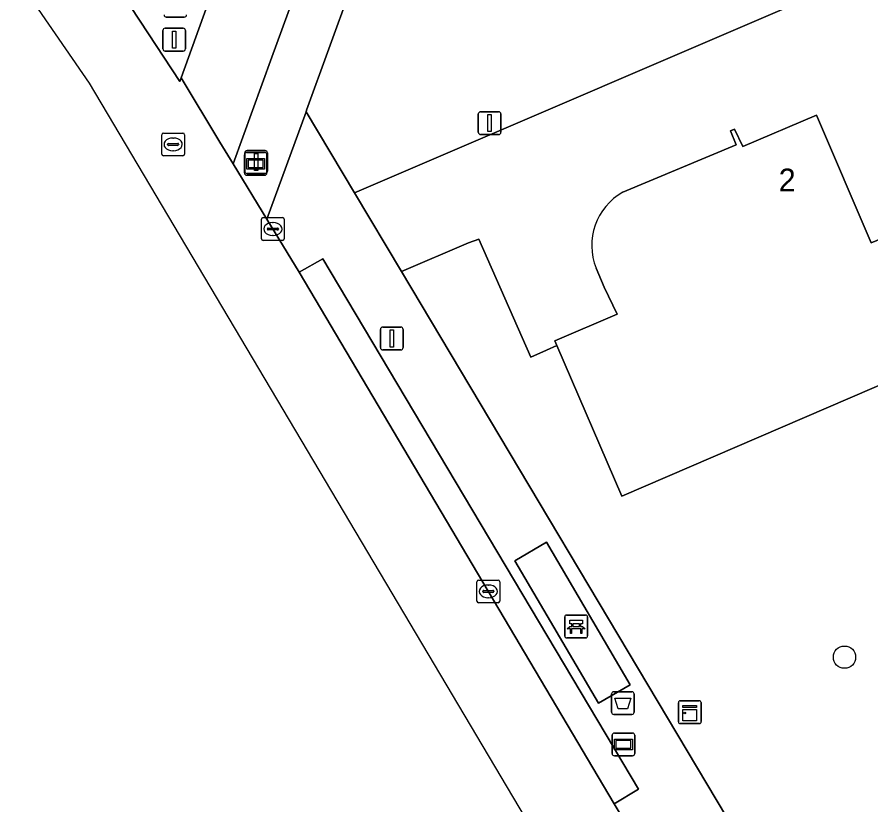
# Model space of a CAD drawing. Extents: x 156661 to 157576, y 383570 to 384425.
# Drawn here: x 156665.87 to 156703.3, y 383837.35 to 383871.9 of the extents above; entities that cross this region are included whole.
import ezdxf

# ---------------------------------------------------------------- set-up
doc = ezdxf.new("R2010")
doc.units = 0
for name, color, linetype in [('IMGEO_Afvalbak', 7, 'Continuous'), ('IMGEO_Bank', 7, 'Continuous'), ('IMGEO_Boom', 7, 'Continuous'), ('IMGEO_Fietspad_open', 7, 'Continuous'), ('IMGEO_Groenvoorziening', 7, 'Continuous'), ('IMGEO_Informatiebord', 7, 'Continuous'), ('IMGEO_Kast', 7, 'Continuous'), ('IMGEO_Kolk', 7, 'Continuous'), ('IMGEO_Lichtmast', 7, 'Continuous'), ('IMGEO_OVBaan_gesloten', 7, 'Continuous'), ('IMGEO_Pand', 7, 'Continuous'), ('IMGEO_Pand_nummerreeks', 7, 'Continuous'), ('IMGEO_Rioolput', 7, 'Continuous'), ('IMGEO_Verkeersbordpaal', 7, 'Continuous'), ('IMGEO_Verkeerseiland_groen', 7, 'Continuous'), ('IMGEO_Verkeersregelinstallatiepaal', 7, 'Continuous'), ('IMGEO_Voetpad_open', 7, 'Continuous'), ('IMGEO_Wegwijzer', 7, 'Continuous')]:
    doc.layers.add(name, color=color, linetype=linetype)

msp = doc.modelspace()

# ---------------------------------------------------------------- linework, layer by layer
at = {"layer": 'IMGEO_Afvalbak'}
for p, q in [((156692.03, 383842.313), (156692.82, 383842.313)), ((156692.82, 383842.313), (156692.03, 383842.313)), ((156691.93, 383841.413), (156691.93, 383842.213)), ((156691.93, 383842.213), (156691.93, 383841.413)), ((156692.92, 383842.213), (156692.92, 383841.413)), ((156692.92, 383841.413), (156692.92, 383842.213)), ((156692.82, 383841.313), (156692.03, 383841.313)), ((156692.03, 383841.313), (156692.82, 383841.313))]:
    msp.add_line(p, q, dxfattribs=at)
msp.add_lwpolyline([(156692.073, 383842.027), (156692.777, 383842.027), (156692.628, 383841.557), (156692.222, 383841.557), (156692.073, 383842.027)], dxfattribs=at)
for centre, start, end in [((156692.03, 383842.213), 90, 180), ((156692.03, 383842.213), 90, 180), ((156692.82, 383842.213), 0, 90), ((156692.82, 383842.213), 360, 90), ((156692.03, 383841.413), 180, 270), ((156692.03, 383841.413), 180, 270), ((156692.82, 383841.413), 270, 0), ((156692.82, 383841.413), 270, 0)]:
    msp.add_arc(centre, 0.1, start, end, dxfattribs=at)
at = {"layer": 'IMGEO_Bank'}
for p, q in [((156689.956, 383845.674), (156690.797, 383845.674)), ((156690.797, 383845.674), (156689.956, 383845.674)), ((156689.881, 383844.749), (156689.881, 383845.59)), ((156689.881, 383845.59), (156689.881, 383844.749)), ((156690.19, 383845.18), (156690.19, 383845.286)), ((156690.234, 383845.286), (156690.234, 383845.18)), ((156690.522, 383845.292), (156690.24, 383845.292)), ((156690.528, 383845.18), (156690.528, 383845.286)), ((156690.572, 383845.286), (156690.572, 383845.18)), ((156690.881, 383845.599), (156690.881, 383844.758)), ((156690.881, 383844.758), (156690.881, 383845.599)), ((156690.578, 383845.072), (156690.185, 383845.072)), ((156690.24, 383845.174), (156690.522, 383845.174)), ((156690.806, 383844.674), (156689.965, 383844.674)), ((156689.965, 383844.674), (156690.806, 383844.674))]:
    msp.add_line(p, q, dxfattribs=at)
for points in [[(156690.184, 383845.292), (156690.098, 383845.292), (156690.098, 383845.453), (156690.661, 383845.453), (156690.661, 383845.292), (156690.578, 383845.292)], [(156690.128, 383845.072), (156689.986, 383845.072), (156690.098, 383845.174), (156690.184, 383845.174)], [(156690.178, 383845.065), (156690.178, 383844.858), (156690.135, 383844.858), (156690.135, 383845.065)], [(156690.578, 383845.174), (156690.661, 383845.174), (156690.773, 383845.072), (156690.634, 383845.072)], [(156690.628, 383845.065), (156690.628, 383844.858), (156690.584, 383844.858), (156690.584, 383845.065)]]:
    msp.add_lwpolyline(points, dxfattribs=at)
for centre, radius, start, end in [((156689.959, 383845.596), 0.0779, 92.4484, 184.2845), ((156689.959, 383845.596), 0.0779, 92.4484, 184.2845), ((156690.803, 383845.596), 0.0779, 2.4484, 94.2845), ((156690.803, 383845.596), 0.0779, 2.4484, 94.2845), ((156690.183, 383845.285), 0.00671, 2.8957, 87.1043), ((156690.24, 383845.285), 0.00671, 92.8957, 177.1043), ((156690.522, 383845.285), 0.00671, 2.8957, 87.1043), ((156690.579, 383845.285), 0.00671, 92.8957, 177.1043), ((156690.128, 383845.065), 0.00671, 2.8957, 87.1043), ((156690.185, 383845.065), 0.00671, 92.8957, 177.1043), ((156690.183, 383845.181), 0.00671, 272.8957, 357.1043), ((156690.24, 383845.181), 0.00671, 182.8957, 267.1043), ((156690.522, 383845.181), 0.00671, 272.8957, 357.1043), ((156690.579, 383845.181), 0.00671, 182.8957, 267.1043), ((156690.577, 383845.065), 0.00671, 2.8957, 87.1043), ((156690.634, 383845.065), 0.00671, 92.8957, 177.1043), ((156689.959, 383844.752), 0.0779, 182.4484, 274.2845), ((156689.959, 383844.752), 0.0779, 182.4484, 274.2845), ((156690.803, 383844.752), 0.0779, 272.4484, 4.2845), ((156690.803, 383844.752), 0.0779, 272.4484, 4.2845)]:
    msp.add_arc(centre, radius, start, end, dxfattribs=at)
at = {"layer": 'IMGEO_Boom'}
msp.add_circle((156702.146, 383843.826), 0.489, dxfattribs=at)
at = {"layer": 'IMGEO_Fietspad_open'}
msp.add_lwpolyline([(156734.031, 384037.106), (156712.164, 383977.004), (156687.083, 383907.958), (156686.019, 383905.021), (156685.19, 383902.73), (156682.699, 383895.852), (156679.844, 383887.968), (156675.39, 383875.671), (156674.868, 383874.229), (156674.867, 383874.227), (156673.061, 383869.241), (156674.754, 383866.418), (156675.34, 383865.46), (156677.045, 383870.138), (156690.408, 383906.735), (156701.659, 383937.694), (156709.217, 383958.49), (156716.373, 383978.18), (156737.507, 384036.302)], dxfattribs=at)
at = {"layer": 'IMGEO_Groenvoorziening'}
msp.add_lwpolyline([(156690.731, 383881.92), (156682.477, 383878.585), (156678.565, 383867.81), (156678.542, 383867.746), (156680.663, 383864.185), (156702.384, 383873.524), (156703.031, 383873.802), (156702.732, 383874)], close=True, dxfattribs=at)
msp.add_lwpolyline([(156704.398, 383856.067), (156692.389, 383850.886), (156689.54, 383857.489), (156689.081, 383857.291), (156688.398, 383856.983), (156686.114, 383862.164), (156685.661, 383861.994), (156682.717, 383860.738), (156696.966, 383836.824), (156704.38, 383824.151), (156702.342, 383822.975), (156699.159, 383829.422), (156695.097, 383835.702), (156693.596, 383834.801), (156695.249, 383832.046), (156695.872, 383830.999), (156695.764, 383830.919), (156715.066, 383798.361)], dxfattribs=at)
at = {"layer": 'IMGEO_Informatiebord'}
for p, q in [((156675.934, 383865.963), (156676.724, 383865.963)), ((156676.724, 383865.963), (156675.934, 383865.963)), ((156675.834, 383865.063), (156675.834, 383865.863)), ((156675.834, 383865.863), (156675.834, 383865.063)), ((156676.824, 383865.863), (156676.824, 383865.063)), ((156676.824, 383865.063), (156676.824, 383865.863)), ((156676.724, 383864.963), (156675.934, 383864.963)), ((156675.934, 383864.963), (156676.724, 383864.963))]:
    msp.add_line(p, q, dxfattribs=at)
for points in [[(156675.935, 383865.695), (156676.723, 383865.695), (156676.723, 383865.231), (156675.935, 383865.231), (156675.935, 383865.695)], [(156676, 383865.63), (156676, 383865.296), (156676.658, 383865.296), (156676.658, 383865.63), (156676, 383865.63)]]:
    msp.add_lwpolyline(points, dxfattribs=at)
for centre, start, end in [((156675.934, 383865.863), 90, 180), ((156675.934, 383865.863), 90, 180), ((156676.724, 383865.863), 0, 90), ((156676.724, 383865.863), 360, 90), ((156675.934, 383865.063), 180, 270), ((156675.934, 383865.063), 180, 270), ((156676.724, 383865.063), 270, 0), ((156676.724, 383865.063), 270, 0)]:
    msp.add_arc(centre, 0.1, start, end, dxfattribs=at)
at = {"layer": 'IMGEO_Kast'}
for p, q in [((156694.937, 383841.915), (156695.778, 383841.915)), ((156695.778, 383841.915), (156694.937, 383841.915)), ((156694.862, 383840.99), (156694.862, 383841.831)), ((156694.862, 383841.831), (156694.862, 383840.99)), ((156695.862, 383841.84), (156695.862, 383840.999)), ((156695.862, 383840.999), (156695.862, 383841.84)), ((156695.787, 383840.915), (156694.946, 383840.915)), ((156694.946, 383840.915), (156695.787, 383840.915))]:
    msp.add_line(p, q, dxfattribs=at)
for points in [[(156695.057, 383841.705), (156695.657, 383841.705), (156695.657, 383841.62), (156695.057, 383841.62), (156695.057, 383841.705)], [(156695.057, 383841.53), (156695.657, 383841.53), (156695.657, 383841.041), (156695.057, 383841.041), (156695.057, 383841.53)]]:
    msp.add_lwpolyline(points, dxfattribs=at)
msp.add_circle((156695.141, 383841.379), 0.0377, dxfattribs=at)
for centre, start, end in [((156694.94, 383841.837), 92.4484, 184.2845), ((156694.94, 383841.837), 92.4484, 184.2845), ((156695.784, 383841.837), 2.4484, 94.2845), ((156695.784, 383841.837), 2.4484, 94.2845), ((156694.94, 383840.993), 182.4484, 274.2845), ((156694.94, 383840.993), 182.4484, 274.2845), ((156695.784, 383840.993), 272.4484, 4.2845), ((156695.784, 383840.993), 272.4484, 4.2845)]:
    msp.add_arc(centre, 0.0779, start, end, dxfattribs=at)
at = {"layer": 'IMGEO_Kolk'}
for p, q in [((156676.583, 383862.178), (156676.583, 383863.03)), ((156676.658, 383863.104), (156677.51, 383863.104)), ((156677.071, 383862.884), (156677.096, 383862.884)), ((156677.584, 383863.03), (156677.584, 383862.178)), ((156676.842, 383862.598), (156676.842, 383862.61)), ((156677.28, 383862.561), (156676.882, 383862.561)), ((156676.885, 383862.647), (156677.283, 383862.647)), ((156677.326, 383862.61), (156677.326, 383862.598)), ((156677.094, 383862.324), (156677.069, 383862.324)), ((156677.51, 383862.104), (156676.658, 383862.104)), ((156686.104, 383847.21), (156686.956, 383847.21)), ((156686.029, 383846.284), (156686.029, 383847.136)), ((156686.517, 383846.99), (156686.542, 383846.99)), ((156687.03, 383847.136), (156687.03, 383846.284)), ((156686.288, 383846.704), (156686.288, 383846.716)), ((156686.726, 383846.667), (156686.328, 383846.667)), ((156686.331, 383846.753), (156686.729, 383846.753)), ((156686.54, 383846.43), (156686.515, 383846.43)), ((156686.772, 383846.716), (156686.772, 383846.704)), ((156686.956, 383846.21), (156686.104, 383846.21))]:
    msp.add_line(p, q, dxfattribs=at)
for points in [[(156676.583, 383862.178), (156676.583, 383863.03)], [(156676.658, 383863.104), (156677.51, 383863.104)], [(156677.584, 383863.03), (156677.584, 383862.178)], [(156677.51, 383862.104), (156676.658, 383862.104)], [(156686.104, 383847.21), (156686.956, 383847.21)], [(156686.029, 383846.284), (156686.029, 383847.136)], [(156687.03, 383847.136), (156687.03, 383846.284)], [(156686.956, 383846.21), (156686.104, 383846.21)]]:
    msp.add_lwpolyline(points, dxfattribs=at)
for centre, radius, start, end in [((156676.66, 383863.028), 0.0765, 91.552, 178.448), ((156676.66, 383863.028), 0.0765, 91.552, 178.448), ((156677.508, 383863.028), 0.0765, 1.552, 88.448), ((156677.508, 383863.028), 0.0765, 1.552, 88.448), ((156676.882, 383862.607), 0.0403, 85.8775, 175.7526), ((156676.879, 383862.597), 0.0366, 178.938, 274.7102), ((156677.283, 383862.604), 0.043, 264.8664, 352.4533), ((156677.287, 383862.609), 0.0386, 1.7309, 96.639), ((156676.66, 383862.18), 0.0765, 181.552, 268.448), ((156676.66, 383862.18), 0.0765, 181.552, 268.448), ((156677.508, 383862.18), 0.0765, 271.552, 358.448), ((156677.508, 383862.18), 0.0765, 271.552, 358.448), ((156686.106, 383847.134), 0.0765, 91.552, 178.448), ((156686.106, 383847.134), 0.0765, 91.552, 178.448), ((156686.954, 383847.134), 0.0765, 1.552, 88.448), ((156686.954, 383847.134), 0.0765, 1.552, 88.448), ((156686.328, 383846.713), 0.0403, 85.8775, 175.7526), ((156686.325, 383846.703), 0.0366, 178.938, 274.7102), ((156686.729, 383846.71), 0.043, 264.8664, 352.4533), ((156686.733, 383846.715), 0.0386, 1.7309, 96.639), ((156686.106, 383846.286), 0.0765, 181.552, 268.448), ((156686.106, 383846.286), 0.0765, 181.552, 268.448), ((156686.954, 383846.286), 0.0765, 271.552, 358.448), ((156686.954, 383846.286), 0.0765, 271.552, 358.448)]:
    msp.add_arc(centre, radius, start, end, dxfattribs=at)
for centre, major_axis, ratio, start_param, end_param in [((156677.07, 383862.604), (-0.387, 0.002), 0.722429, 4.712389, 7.853982), ((156677.095, 383862.604), (-0.39, 0.002), 0.717154, 1.570796, 4.712389), ((156686.516, 383846.71), (-0.387, 0.002), 0.722429, 4.712389, 7.853982), ((156686.541, 383846.71), (-0.39, 0.002), 0.717154, 1.570796, 4.712389)]:
    msp.add_ellipse(centre, major_axis=major_axis, ratio=ratio, start_param=start_param, end_param=end_param, dxfattribs=at)
at = {"layer": 'IMGEO_Lichtmast'}
for p, q in [((156686.192, 383867.748), (156686.982, 383867.748)), ((156686.982, 383867.748), (156686.192, 383867.748)), ((156686.092, 383866.848), (156686.092, 383867.648)), ((156686.092, 383867.648), (156686.092, 383866.848)), ((156687.082, 383867.648), (156687.082, 383866.848)), ((156687.082, 383866.848), (156687.082, 383867.648)), ((156686.982, 383866.748), (156686.192, 383866.748)), ((156686.192, 383866.748), (156686.982, 383866.748)), ((156681.802, 383857.402), (156681.802, 383858.202)), ((156681.802, 383858.202), (156681.802, 383857.402)), ((156681.902, 383858.302), (156682.692, 383858.302)), ((156682.692, 383858.302), (156681.902, 383858.302)), ((156682.792, 383858.202), (156682.792, 383857.402)), ((156682.792, 383857.402), (156682.792, 383858.202)), ((156682.692, 383857.302), (156681.902, 383857.302)), ((156681.902, 383857.302), (156682.692, 383857.302))]:
    msp.add_line(p, q, dxfattribs=at)
for points in [[(156686.512, 383867.623), (156686.662, 383867.623), (156686.662, 383866.873), (156686.512, 383866.873), (156686.512, 383867.623)], [(156682.222, 383858.177), (156682.372, 383858.177), (156682.372, 383857.427), (156682.222, 383857.427), (156682.222, 383858.177)]]:
    msp.add_lwpolyline(points, dxfattribs=at)
for centre, start, end in [((156686.192, 383867.648), 90, 180), ((156686.192, 383867.648), 90, 180), ((156686.982, 383867.648), 0, 90), ((156686.982, 383867.648), 360, 90), ((156686.192, 383866.848), 180, 270), ((156686.192, 383866.848), 180, 270), ((156686.982, 383866.848), 270, 0), ((156686.982, 383866.848), 270, 0), ((156681.902, 383858.202), 90, 180), ((156681.902, 383858.202), 90, 180), ((156682.692, 383858.202), 0, 90), ((156682.692, 383858.202), 360, 90), ((156681.902, 383857.402), 180, 270), ((156681.902, 383857.402), 180, 270), ((156682.692, 383857.402), 270, 0), ((156682.692, 383857.402), 270, 0)]:
    msp.add_arc(centre, 0.1, start, end, dxfattribs=at)
at = {"layer": 'IMGEO_OVBaan_gesloten'}
msp.add_lwpolyline([(156774.683, 383690.665), (156778.033, 383692.126), (156743.737, 383750), (156720.142, 383789.798), (156715.066, 383798.361), (156695.764, 383830.919), (156695.872, 383830.999), (156695.249, 383832.046), (156693.596, 383834.801), (156692.043, 383837.395), (156678.244, 383860.711), (156676.825, 383863.032), (156675.34, 383865.46), (156674.754, 383866.418), (156673.061, 383869.241), (156673.001, 383869.075), (156671.262, 383871.721), (156669.536, 383874.347), (156666.5, 383872.689), (156669.035, 383868.996), (156694.501, 383826.069), (156728.444, 383768.526)], close=True, dxfattribs=at)
at = {"layer": 'IMGEO_Pand'}
msp.add_lwpolyline([(156691.257, 383860.885), (156691.614, 383860.059), (156692.177, 383858.875), (156689.45, 383857.699), (156689.54, 383857.489), (156692.389, 383850.886), (156704.398, 383856.067), (156709.549, 383858.26), (156709.424, 383858.554), (156709.056, 383858.397), (156706.995, 383863.214), (156707.363, 383863.372), (156707.237, 383863.666), (156703.808, 383862.199), (156703.32, 383861.991), (156700.923, 383867.6), (156697.694, 383866.219), (156697.33, 383866.987), (156697.143, 383866.907), (156697.403, 383866.292), (156692.428, 383864.216)], dxfattribs=at)
msp.add_arc((156693.739, 383861.884), 2.676, 119.3437, 201.9185, dxfattribs=at)
at = {"layer": 'IMGEO_Rioolput'}
for p, q in [((156672.211, 383865.887), (156672.211, 383866.739)), ((156672.286, 383866.813), (156673.138, 383866.813)), ((156673.212, 383866.739), (156673.212, 383865.887)), ((156672.47, 383866.307), (156672.47, 383866.319)), ((156672.908, 383866.27), (156672.51, 383866.27)), ((156672.513, 383866.356), (156672.911, 383866.356)), ((156672.699, 383866.593), (156672.724, 383866.593)), ((156672.954, 383866.319), (156672.954, 383866.307)), ((156672.722, 383866.033), (156672.697, 383866.033)), ((156673.138, 383865.813), (156672.286, 383865.813))]:
    msp.add_line(p, q, dxfattribs=at)
for points in [[(156672.211, 383865.887), (156672.211, 383866.739)], [(156672.286, 383866.813), (156673.138, 383866.813)], [(156673.212, 383866.739), (156673.212, 383865.887)], [(156673.138, 383865.813), (156672.286, 383865.813)]]:
    msp.add_lwpolyline(points, dxfattribs=at)
for centre, radius, start, end in [((156672.288, 383866.737), 0.0765, 91.552, 178.448), ((156672.288, 383866.737), 0.0765, 91.552, 178.448), ((156673.136, 383866.737), 0.0765, 1.552, 88.448), ((156673.136, 383866.737), 0.0765, 1.552, 88.448), ((156672.51, 383866.316), 0.0403, 85.8775, 175.7526), ((156672.507, 383866.306), 0.0366, 178.938, 274.7102), ((156672.911, 383866.313), 0.043, 264.8664, 352.4533), ((156672.915, 383866.318), 0.0386, 1.7309, 96.639), ((156672.288, 383865.889), 0.0765, 181.552, 268.448), ((156672.288, 383865.889), 0.0765, 181.552, 268.448), ((156673.136, 383865.889), 0.0765, 271.552, 358.448), ((156673.136, 383865.889), 0.0765, 271.552, 358.448)]:
    msp.add_arc(centre, radius, start, end, dxfattribs=at)
for centre, major_axis, ratio, start_param, end_param in [((156672.698, 383866.313), (-0.387, 0.002), 0.722429, 4.712389, 7.853982), ((156672.723, 383866.313), (-0.39, 0.002), 0.717154, 1.570796, 4.712389)]:
    msp.add_ellipse(centre, major_axis=major_axis, ratio=ratio, start_param=start_param, end_param=end_param, dxfattribs=at)
at = {"layer": 'IMGEO_Verkeersbordpaal'}
for p, q in [((156673.201, 383871.898), (156672.411, 383871.898)), ((156672.411, 383871.898), (156673.201, 383871.898))]:
    msp.add_line(p, q, dxfattribs=at)
for centre, start, end in [((156672.411, 383871.998), 180, 270), ((156672.411, 383871.998), 180, 270), ((156673.201, 383871.998), 270, 0), ((156673.201, 383871.998), 270, 0)]:
    msp.add_arc(centre, 0.1, start, end, dxfattribs=at)
at = {"layer": 'IMGEO_Verkeerseiland_groen'}
msp.add_lwpolyline([(156679.844, 383887.968), (156676.643, 383888.338), (156676.494, 383887.977), (156675.317, 383888.605), (156675.289, 383888.572), (156672.38, 383885.288), (156671.404, 383884.364), (156669.961, 383882.999), (156665.869, 383879.494), (156667.479, 383877.222), (156669.536, 383874.347), (156671.262, 383871.721), (156673.001, 383869.075), (156673.061, 383869.241), (156674.867, 383874.227), (156674.102, 383875.538), (156675.126, 383876.162), (156675.39, 383875.671)], close=True, dxfattribs=at)
at = {"layer": 'IMGEO_Verkeersregelinstallatiepaal'}
for p, q in [((156672.261, 383870.508), (156672.261, 383871.308)), ((156672.261, 383871.308), (156672.261, 383870.508)), ((156672.361, 383871.408), (156673.151, 383871.408)), ((156673.151, 383871.408), (156672.361, 383871.408)), ((156673.251, 383871.308), (156673.251, 383870.508)), ((156673.251, 383870.508), (156673.251, 383871.308)), ((156673.151, 383870.408), (156672.361, 383870.408)), ((156672.361, 383870.408), (156673.151, 383870.408)), ((156675.853, 383865.14), (156675.853, 383865.94)), ((156675.853, 383865.94), (156675.853, 383865.14)), ((156675.953, 383866.04), (156676.743, 383866.04)), ((156676.743, 383866.04), (156675.953, 383866.04)), ((156676.843, 383865.94), (156676.843, 383865.14)), ((156676.843, 383865.14), (156676.843, 383865.94)), ((156676.743, 383865.04), (156675.953, 383865.04)), ((156675.953, 383865.04), (156676.743, 383865.04))]:
    msp.add_line(p, q, dxfattribs=at)
for points in [[(156672.681, 383871.283), (156672.831, 383871.283), (156672.831, 383870.533), (156672.681, 383870.533), (156672.681, 383871.283)], [(156676.273, 383865.915), (156676.423, 383865.915), (156676.423, 383865.165), (156676.273, 383865.165), (156676.273, 383865.915)]]:
    msp.add_lwpolyline(points, dxfattribs=at)
for centre, start, end in [((156672.361, 383871.308), 90, 180), ((156672.361, 383871.308), 90, 180), ((156673.151, 383871.308), 0, 90), ((156673.151, 383871.308), 360, 90), ((156672.361, 383870.508), 180, 270), ((156672.361, 383870.508), 180, 270), ((156673.151, 383870.508), 270, 0), ((156673.151, 383870.508), 270, 0), ((156675.953, 383865.94), 90, 180), ((156675.953, 383865.94), 90, 180), ((156676.743, 383865.94), 0, 90), ((156676.743, 383865.94), 360, 90), ((156675.953, 383865.14), 180, 270), ((156675.953, 383865.14), 180, 270), ((156676.743, 383865.14), 270, 0), ((156676.743, 383865.14), 270, 0)]:
    msp.add_arc(centre, 0.1, start, end, dxfattribs=at)
at = {"layer": 'IMGEO_Voetpad_open'}
for points in [[(156737.507, 384036.302), (156716.373, 383978.18), (156709.217, 383958.49), (156701.659, 383937.694), (156690.408, 383906.735), (156677.045, 383870.138), (156675.34, 383865.46), (156676.825, 383863.032), (156678.542, 383867.746), (156678.565, 383867.81), (156682.477, 383878.585), (156685.05, 383885.669), (156685.231, 383886.168), (156686.812, 383890.508), (156687.008, 383891.046), (156692.453, 383905.972), (156693.23, 383908.111), (156693.984, 383910.189), (156695.166, 383913.444), (156695.763, 383915.089), (156718.784, 383978.494), (156726.363, 383999.343), (156726.961, 384000.99), (156740.015, 384036.902)], [(156702.384, 383873.524), (156680.663, 383864.185), (156682.717, 383860.738), (156685.661, 383861.994), (156686.114, 383862.164), (156688.398, 383856.983), (156689.081, 383857.291), (156689.54, 383857.489), (156689.45, 383857.699), (156692.177, 383858.875), (156691.614, 383860.059), (156691.257, 383860.885)], [(156697.403, 383866.292), (156697.143, 383866.907), (156697.33, 383866.987), (156697.694, 383866.219), (156700.923, 383867.6), (156703.32, 383861.991), (156703.808, 383862.199), (156707.237, 383863.666), (156707.654, 383863.85), (156727.201, 383849.634), (156729.684, 383847.837), (156734.285, 383844.531), (156738.813, 383848.462), (156739.736, 383849.264), (156740.115, 383849.593)], [(156692.428, 383864.216), (156697.403, 383866.292)]]:
    msp.add_lwpolyline(points, dxfattribs=at)
for points in [[(156682.717, 383860.738), (156680.663, 383864.185), (156678.542, 383867.746), (156676.825, 383863.032), (156678.244, 383860.711), (156679.277, 383861.3), (156693.107, 383838.038), (156692.043, 383837.395), (156693.596, 383834.801), (156695.097, 383835.702), (156696.966, 383836.824)], [(156678.244, 383860.711), (156692.043, 383837.395), (156693.107, 383838.038), (156679.277, 383861.3)], [(156689.08, 383848.865), (156692.748, 383842.618), (156691.363, 383841.805), (156687.695, 383848.052)], [(156687.695, 383848.052), (156691.363, 383841.805), (156692.748, 383842.618), (156689.08, 383848.865)]]:
    msp.add_lwpolyline(points, close=True, dxfattribs=at)
msp.add_arc((156693.739, 383861.884), 2.676, 119.3437, 201.9185, dxfattribs=at)
at = {"layer": 'IMGEO_Wegwijzer'}
for p, q in [((156692.059, 383840.499), (156692.849, 383840.499)), ((156692.849, 383840.499), (156692.059, 383840.499)), ((156691.959, 383839.599), (156691.959, 383840.399)), ((156691.959, 383840.399), (156691.959, 383839.599)), ((156692.949, 383840.399), (156692.949, 383839.599)), ((156692.949, 383839.599), (156692.949, 383840.399)), ((156692.849, 383839.499), (156692.059, 383839.499)), ((156692.059, 383839.499), (156692.849, 383839.499))]:
    msp.add_line(p, q, dxfattribs=at)
for points in [[(156692.06, 383840.231), (156692.848, 383840.231), (156692.848, 383839.767), (156692.06, 383839.767), (156692.06, 383840.231)], [(156692.125, 383840.166), (156692.125, 383839.832), (156692.783, 383839.832), (156692.783, 383840.166), (156692.125, 383840.166)]]:
    msp.add_lwpolyline(points, dxfattribs=at)
for centre, start, end in [((156692.059, 383840.399), 90, 180), ((156692.059, 383840.399), 90, 180), ((156692.849, 383840.399), 0, 90), ((156692.849, 383840.399), 360, 90), ((156692.059, 383839.599), 180, 270), ((156692.059, 383839.599), 180, 270), ((156692.849, 383839.599), 270, 0), ((156692.849, 383839.599), 270, 0)]:
    msp.add_arc(centre, 0.1, start, end, dxfattribs=at)

# ---------------------------------------------------------------- texts
at = {"layer": 'IMGEO_Pand_nummerreeks'}
msp.add_text('2', height=1, dxfattribs=at).set_placement((156699.26, 383864.253))

doc.saveas('drawing.dxf')
